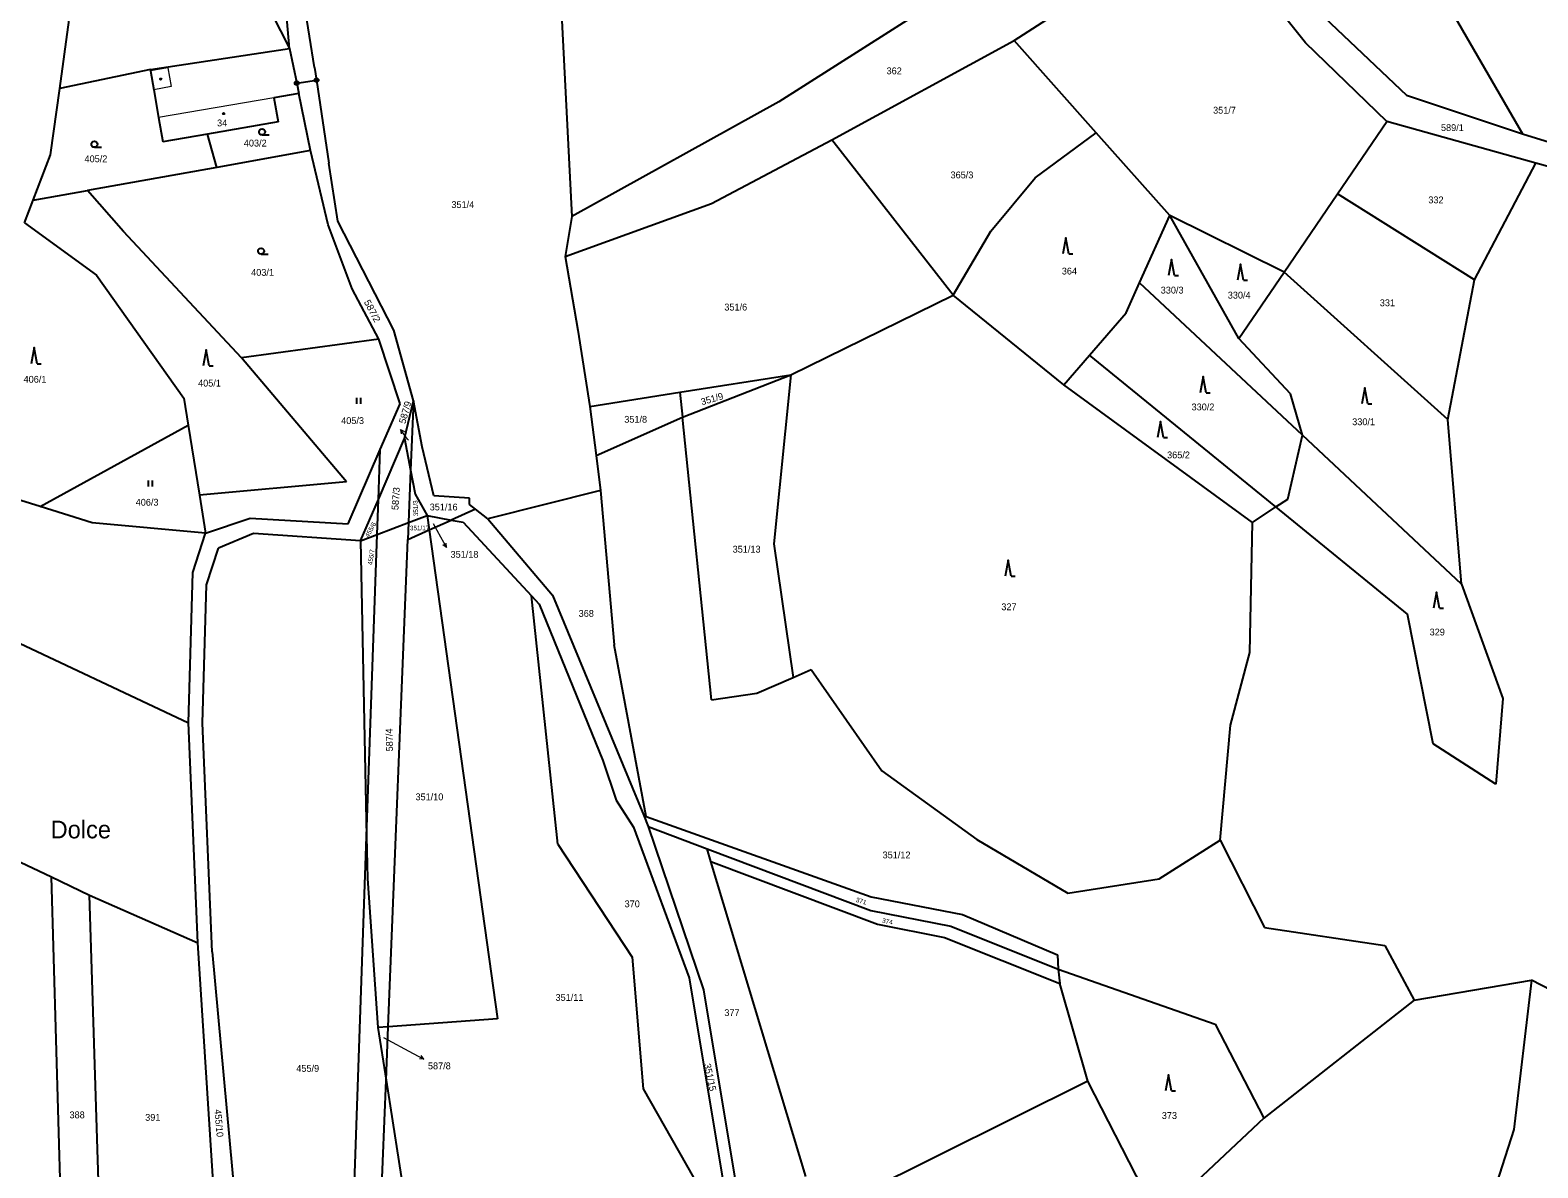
# Model space of a CAD drawing. Extents: x -664548 to -662415, y -1069720 to -1068208.
# Drawn here: x -663609.5 to -663233.8, y -1069397.8 to -1069114.5 of the extents above; entities that cross this region are included whole.
import ezdxf
from ezdxf.enums import TextEntityAlignment as Align

# ---------------------------------------------------------------- set-up
doc = ezdxf.new("R2010")
doc.units = 0
doc.header["$LTSCALE"] = 0.68
for name, color, linetype, lineweight in [('1', 7, 'Continuous', 25), ('3', 7, 'Continuous', 25), ('4', 7, 'Continuous', 13), ('5', 7, 'Continuous', 25), ('7', 7, 'Continuous', 13), ('8', 7, 'Continuous', 25)]:
    doc.layers.add(name, color=color, linetype=linetype, lineweight=lineweight)
doc.layers.add('2', color=7, linetype='Continuous')

msp = doc.modelspace()

# ---------------------------------------------------------------- linework, layer by layer
at = {"layer": '1'}
for p, q in [((-663290.69, -1069048.61), (-663237.59, -1069140.27)), ((-663562.04, -1069085.25), (-663544.88, -1069119.07)), ((-663364.35, -1069117.05), (-663316.66, -1069086.41)), ((-663291.71, -1069117.65), (-663316.66, -1069086.41)), ((-663371.11, -1069099.37), (-663422.94, -1069132.37)), ((-663544.88, -1069119.07), (-663545.93, -1069107.64)), ((-663538.64, -1069123.79), (-663541.13, -1069108.16)), ((-663477.22, -1069108.85), (-663474.57, -1069160.93)), ((-663288.57, -1069109.85), (-663266.5, -1069130.7)), ((-663602.17, -1069129.03), (-663599.82, -1069111.91)), ((-663409.77, -1069141.77), (-663364.35, -1069117.05)), ((-663343.84, -1069140.07), (-663364.35, -1069117.05)), ((-663271.46, -1069137.23), (-663291.71, -1069117.65)), ((-663579.59, -1069124.25), (-663544.88, -1069119.07)), ((-663544.88, -1069119.07), (-663543.12, -1069127.66)), ((-663579.59, -1069124.25), (-663602.17, -1069129.03)), ((-663579.59, -1069124.25), (-663579.52, -1069124.64)), ((-663579.52, -1069124.64), (-663578.7, -1069129.37)), ((-663538.64, -1069123.79), (-663538.17, -1069126.92)), ((-663604.44, -1069145.56), (-663602.17, -1069129.03)), ((-663578.7, -1069129.37), (-663577.52, -1069136.2)), ((-663543.12, -1069127.66), (-663538.17, -1069126.92)), ((-663543.12, -1069127.66), (-663542.59, -1069130.23)), ((-663538.17, -1069126.92), (-663535.09, -1069147.57)), ((-663542.59, -1069130.23), (-663548.81, -1069131.32)), ((-663548.81, -1069131.32), (-663547.77, -1069137.33)), ((-663539.64, -1069144.45), (-663542.59, -1069130.23)), ((-663422.94, -1069132.37), (-663474.57, -1069160.93)), ((-663266.5, -1069130.7), (-663237.59, -1069140.27)), ((-663577.52, -1069136.2), (-663576.47, -1069142.3)), ((-663547.77, -1069137.33), (-663565.34, -1069140.37)), ((-663283.71, -1069155.22), (-663271.46, -1069137.23)), ((-663234.3, -1069147.61), (-663271.46, -1069137.23)), ((-663565.34, -1069140.37), (-663576.47, -1069142.3)), ((-663563.03, -1069148.65), (-663565.34, -1069140.37)), ((-663359.12, -1069151.28), (-663343.84, -1069140.07)), ((-663325.5, -1069160.64), (-663343.84, -1069140.07)), ((-663237.59, -1069140.27), (-663178.99, -1069158.74)), ((-663539.64, -1069144.45), (-663563.03, -1069148.65)), ((-663535.31, -1069162.97), (-663539.64, -1069144.45)), ((-663439.71, -1069157.68), (-663409.77, -1069141.77)), ((-663379.48, -1069180.49), (-663409.77, -1069141.77)), ((-663608.81, -1069156.86), (-663604.44, -1069145.56)), ((-663563.03, -1069148.65), (-663595.24, -1069154.43)), ((-663532.83, -1069162.06), (-663535.09, -1069147.57)), ((-663249.56, -1069176.69), (-663234.3, -1069147.61)), ((-663177.21, -1069163.55), (-663234.3, -1069147.61)), ((-663370.12, -1069164.56), (-663359.12, -1069151.28)), ((-663608.81, -1069156.86), (-663595.24, -1069154.43)), ((-663297, -1069174.73), (-663283.71, -1069155.22)), ((-663249.56, -1069176.69), (-663283.71, -1069155.22)), ((-663610.98, -1069162.48), (-663608.81, -1069156.86)), ((-663476.23, -1069170.82), (-663439.71, -1069157.68)), ((-663610.98, -1069162.48), (-663593.01, -1069175.48)), ((-663529.26, -1069178.93), (-663535.31, -1069162.97)), ((-663518.87, -1069189.24), (-663532.83, -1069162.06)), ((-663474.57, -1069160.93), (-663476.23, -1069170.82)), ((-663333.06, -1069177.37), (-663325.5, -1069160.64)), ((-663297, -1069174.73), (-663325.5, -1069160.64)), ((-663308.3, -1069191.31), (-663325.5, -1069160.64)), ((-663379.48, -1069180.49), (-663370.12, -1069164.56)), ((-663476.23, -1069170.82), (-663473.06, -1069189.17)), ((-663308.3, -1069191.31), (-663297, -1069174.73)), ((-663256.27, -1069211.46), (-663297, -1069174.73)), ((-663593.01, -1069175.48), (-663571.28, -1069206.11)), ((-663522.61, -1069191.44), (-663529.26, -1069178.93)), ((-663336.44, -1069184.86), (-663333.06, -1069177.37)), ((-663292.46, -1069215.37), (-663333.06, -1069177.37)), ((-663256.27, -1069211.46), (-663249.56, -1069176.69)), ((-663419.93, -1069200.35), (-663379.48, -1069180.49)), ((-663351.9, -1069202.8), (-663379.48, -1069180.49)), ((-663345.54, -1069195.42), (-663336.44, -1069184.86)), ((-663514.04, -1069206.76), (-663518.87, -1069189.24)), ((-663473.06, -1069189.17), (-663470.04, -1069208.19)), ((-663522.61, -1069191.44), (-663556.83, -1069196.07)), ((-663517.37, -1069207.51), (-663522.61, -1069191.44)), ((-663295.44, -1069205.04), (-663308.3, -1069191.31)), ((-663530.7, -1069226.98), (-663556.83, -1069196.07)), ((-663351.9, -1069202.8), (-663345.54, -1069195.42)), ((-663299.07, -1069233.24), (-663345.54, -1069195.42)), ((-663447.64, -1069204.68), (-663419.93, -1069200.35)), ((-663447, -1069210.85), (-663419.93, -1069200.35)), ((-663419.93, -1069200.35), (-663424.2, -1069242.41)), ((-663470.04, -1069208.19), (-663447.64, -1069204.68)), ((-663447.64, -1069204.68), (-663447, -1069210.85)), ((-663304.9, -1069237.09), (-663351.9, -1069202.8)), ((-663292.46, -1069215.37), (-663295.44, -1069205.04)), ((-663571.28, -1069206.11), (-663570.19, -1069212.83)), ((-663522.32, -1069218.96), (-663517.37, -1069207.51)), ((-663516.21, -1069216.22), (-663514.04, -1069206.76)), ((-663514.04, -1069206.76), (-663514.74, -1069224.08)), ((-663511.85, -1069218.23), (-663514.04, -1069206.76)), ((-663470.04, -1069208.19), (-663468.5, -1069220.43)), ((-663607.07, -1069233.13), (-663570.19, -1069212.83)), ((-663570.19, -1069212.83), (-663567.36, -1069230.28)), ((-663468.5, -1069220.43), (-663447, -1069210.85)), ((-663439.75, -1069281.24), (-663447, -1069210.85)), ((-663252.8, -1069252.48), (-663256.27, -1069211.46)), ((-663522.76, -1069231.36), (-663516.21, -1069216.22)), ((-663516.21, -1069216.22), (-663514.74, -1069224.08)), ((-663252.8, -1069252.48), (-663292.46, -1069215.37)), ((-663530.32, -1069237.45), (-663522.32, -1069218.96)), ((-663522.76, -1069231.36), (-663522.32, -1069218.96)), ((-663508.95, -1069230.5), (-663511.85, -1069218.23)), ((-663514.74, -1069224.08), (-663515.26, -1069237.13)), ((-663514.74, -1069224.08), (-663513.62, -1069230.04)), ((-663468.5, -1069220.43), (-663467.4, -1069229.1)), ((-663530.7, -1069226.98), (-663567.36, -1069230.28)), ((-663607.07, -1069233.13), (-663620, -1069229.07)), ((-663567.36, -1069230.28), (-663565.81, -1069239.8)), ((-663527.21, -1069241.64), (-663522.76, -1069231.36)), ((-663523.07, -1069240.08), (-663522.76, -1069231.36)), ((-663513.62, -1069230.04), (-663510.62, -1069235.37)), ((-663500.08, -1069231.07), (-663508.95, -1069230.5)), ((-663500.08, -1069232.65), (-663500.08, -1069231.07)), ((-663467.4, -1069229.1), (-663495.47, -1069236.2)), ((-663467.4, -1069229.1), (-663463.99, -1069267.55)), ((-663594.1, -1069237.21), (-663607.07, -1069233.13)), ((-663515.26, -1069237.13), (-663510.62, -1069235.37)), ((-663510.62, -1069235.37), (-663510.12, -1069238.95)), ((-663510.62, -1069235.37), (-663504.58, -1069236.49)), ((-663498.57, -1069233.82), (-663504.58, -1069236.49)), ((-663498.57, -1069233.82), (-663500.08, -1069232.65)), ((-663495.47, -1069236.2), (-663498.57, -1069233.82)), ((-663304.9, -1069237.09), (-663299.07, -1069233.24)), ((-663266.27, -1069259.94), (-663299.07, -1069233.24)), ((-663565.81, -1069239.8), (-663594.1, -1069237.21)), ((-663565.81, -1069239.8), (-663554.72, -1069236.01)), ((-663554.72, -1069236.01), (-663530.32, -1069237.45)), ((-663523.07, -1069240.08), (-663515.26, -1069237.13)), ((-663515.26, -1069237.13), (-663515.43, -1069241.31)), ((-663510.12, -1069238.95), (-663493.06, -1069360.76)), ((-663504.58, -1069236.49), (-663501.66, -1069237.03)), ((-663501.66, -1069237.03), (-663484.59, -1069255.39)), ((-663495.47, -1069236.2), (-663479.37, -1069255.2)), ((-663305.57, -1069269.49), (-663304.9, -1069237.09)), ((-663568.97, -1069249.55), (-663565.81, -1069239.8)), ((-663553.89, -1069239.86), (-663562.6, -1069243.53)), ((-663527.21, -1069241.64), (-663553.89, -1069239.86)), ((-663527.21, -1069241.64), (-663523.07, -1069240.08)), ((-663527.21, -1069241.64), (-663525.71, -1069315.33)), ((-663525.71, -1069315.33), (-663523.07, -1069240.08)), ((-663520.3, -1069362.69), (-663515.43, -1069241.31)), ((-663424.2, -1069242.41), (-663419.42, -1069275.68)), ((-663565.56, -1069252.65), (-663562.6, -1069243.53)), ((-663570.12, -1069287), (-663568.97, -1069249.55)), ((-663566.61, -1069287.11), (-663565.56, -1069252.65)), ((-663252.8, -1069252.48), (-663242.55, -1069280.91)), ((-663478.06, -1069317.22), (-663484.59, -1069255.39)), ((-663484.59, -1069255.39), (-663482.65, -1069257.48)), ((-663482.65, -1069257.48), (-663466.81, -1069296.42)), ((-663479.37, -1069255.2), (-663456.64, -1069310.09)), ((-663259.93, -1069292.26), (-663266.27, -1069259.94)), ((-663620.38, -1069263.31), (-663570.12, -1069287)), ((-663456.03, -1069310.31), (-663463.99, -1069267.55)), ((-663310.38, -1069287.58), (-663305.57, -1069269.49)), ((-663428.41, -1069279.64), (-663419.42, -1069275.68)), ((-663419.42, -1069275.68), (-663414.92, -1069273.69)), ((-663414.92, -1069273.69), (-663397.26, -1069298.97)), ((-663439.75, -1069281.24), (-663428.41, -1069279.64)), ((-663242.55, -1069280.91), (-663244.28, -1069302.3)), ((-663567.74, -1069341.82), (-663570.12, -1069287)), ((-663564.14, -1069344.05), (-663566.61, -1069287.11)), ((-663312.95, -1069316.19), (-663310.38, -1069287.58)), ((-663244.28, -1069302.3), (-663259.93, -1069292.26)), ((-663466.81, -1069296.42), (-663463.52, -1069306.28)), ((-663397.26, -1069298.97), (-663373.63, -1069316.04)), ((-663463.52, -1069306.28), (-663459.22, -1069312.98)), ((-663456.64, -1069310.09), (-663456.03, -1069310.31)), ((-663456.64, -1069310.09), (-663455.52, -1069312.82)), ((-663456.03, -1069310.31), (-663399.91, -1069330.35)), ((-663459.22, -1069312.98), (-663445.32, -1069350.54)), ((-663455.52, -1069312.82), (-663441.76, -1069353.53)), ((-663455.52, -1069312.82), (-663440.82, -1069318.37)), ((-663533.54, -1069538.23), (-663525.71, -1069315.33)), ((-663525.71, -1069315.33), (-663525.5, -1069325.78)), ((-663478.06, -1069317.22), (-663459.53, -1069345.4)), ((-663373.63, -1069316.04), (-663350.9, -1069329.44)), ((-663328.15, -1069325.88), (-663312.95, -1069316.19)), ((-663312.95, -1069316.19), (-663301.93, -1069338)), ((-663613.49, -1069320.97), (-663604.26, -1069325.38)), ((-663439.87, -1069321.52), (-663440.82, -1069318.37)), ((-663439.87, -1069321.52), (-663398.4, -1069337.17)), ((-663416.26, -1069400.01), (-663439.87, -1069321.52)), ((-663604.26, -1069325.38), (-663594.75, -1069329.92)), ((-663601.1, -1069432.51), (-663604.26, -1069325.38)), ((-663525.5, -1069325.78), (-663522.87, -1069362.87)), ((-663350.9, -1069329.44), (-663328.15, -1069325.88)), ((-663594.75, -1069329.92), (-663567.74, -1069341.82)), ((-663591.5, -1069432.04), (-663594.75, -1069329.92)), ((-663399.91, -1069330.35), (-663377.19, -1069334.75)), ((-663377.19, -1069334.75), (-663353.55, -1069344.77)), ((-663398.4, -1069337.17), (-663381.65, -1069340.44)), ((-663381.65, -1069340.44), (-663352.91, -1069351.95)), ((-663380.06, -1069337.68), (-663353.34, -1069348.38)), ((-663301.93, -1069338), (-663271.97, -1069342.43)), ((-663562.07, -1069430.61), (-663567.74, -1069341.82)), ((-663564.14, -1069344.05), (-663556.21, -1069430.9)), ((-663271.97, -1069342.43), (-663264.64, -1069356.09)), ((-663459.53, -1069345.4), (-663456.74, -1069378.18)), ((-663353.55, -1069344.77), (-663353.34, -1069348.38)), ((-663445.32, -1069350.54), (-663434.06, -1069418.05)), ((-663353.34, -1069348.38), (-663314.26, -1069362.06)), ((-663353.34, -1069348.38), (-663352.91, -1069351.95)), ((-663264.64, -1069356.09), (-663235.38, -1069351.09)), ((-663235.38, -1069351.09), (-663239.78, -1069388.33)), ((-663213.09, -1069362.7), (-663235.38, -1069351.09)), ((-663441.76, -1069353.53), (-663432.72, -1069407.43)), ((-663345.95, -1069376.22), (-663352.91, -1069351.95)), ((-663264.64, -1069356.09), (-663302.13, -1069385.5)), ((-663520.3, -1069362.69), (-663522.87, -1069362.87)), ((-663522.87, -1069362.87), (-663520.83, -1069375.97)), ((-663520.83, -1069375.97), (-663520.3, -1069362.69)), ((-663493.06, -1069360.76), (-663520.3, -1069362.69)), ((-663314.26, -1069362.06), (-663302.13, -1069385.5)), ((-663527.43, -1069540.73), (-663520.83, -1069375.97)), ((-663520.83, -1069375.97), (-663510.43, -1069442.65)), ((-663456.74, -1069378.18), (-663434.06, -1069418.05)), ((-663345.95, -1069376.22), (-663402.37, -1069404.33)), ((-663328.48, -1069410.22), (-663345.95, -1069376.22)), ((-663302.13, -1069385.5), (-663328.48, -1069410.22)), ((-663239.78, -1069388.33), (-663255.97, -1069438.48))]:
    msp.add_line(p, q, dxfattribs=at)
for points in [[(-663556.83, -1069196.07), (-663586.28, -1069164.65), (-663595.24, -1069154.43)], [(-663299.07, -1069233.24), (-663296.08, -1069231.26), (-663292.46, -1069215.37)], [(-663515.43, -1069241.31), (-663510.12, -1069238.95), (-663504.58, -1069236.49)], [(-663440.82, -1069318.37), (-663400, -1069333.78), (-663380.06, -1069337.68)]]:
    msp.add_lwpolyline(points, dxfattribs=at)
at = {"layer": '3'}
for p, q in [((-663551.743, -1069140.58), (-663549.993, -1069140.58)), ((-663593.533, -1069143.64), (-663591.783, -1069143.64)), ((-663552.003, -1069170.27), (-663550.253, -1069170.27)), ((-663350.72, -1069170.17), (-663349.724, -1069170.17)), ((-663324.39, -1069175.61), (-663323.394, -1069175.61)), ((-663307.12, -1069176.72), (-663306.124, -1069176.72)), ((-663607.76, -1069197.55), (-663606.764, -1069197.55)), ((-663564.91, -1069198.07), (-663563.914, -1069198.07)), ((-663316.48, -1069204.77), (-663315.484, -1069204.77)), ((-663528.151, -1069207.58), (-663528.151, -1069206.08)), ((-663527.15, -1069207.58), (-663527.15, -1069206.08)), ((-663276.15, -1069207.56), (-663275.154, -1069207.56)), ((-663327.12, -1069215.96), (-663326.124, -1069215.96)), ((-663580.051, -1069228.17), (-663580.051, -1069226.67)), ((-663579.05, -1069228.17), (-663579.05, -1069226.67)), ((-663365.05, -1069250.48), (-663364.054, -1069250.48)), ((-663258.31, -1069258.47), (-663257.314, -1069258.47)), ((-663325.07, -1069378.64), (-663324.074, -1069378.64))]:
    msp.add_line(p, q, dxfattribs=at)
for points in [[(-663350.72, -1069170.17), (-663351.47, -1069166.17), (-663352.22, -1069170.17)], [(-663324.39, -1069175.61), (-663325.14, -1069171.61), (-663325.89, -1069175.61)], [(-663307.12, -1069176.72), (-663307.87, -1069172.72), (-663308.62, -1069176.72)], [(-663607.76, -1069197.55), (-663608.51, -1069193.55), (-663609.26, -1069197.55)], [(-663564.91, -1069198.07), (-663565.66, -1069194.07), (-663566.41, -1069198.07)], [(-663316.48, -1069204.77), (-663317.23, -1069200.77), (-663317.98, -1069204.77)], [(-663276.15, -1069207.56), (-663276.9, -1069203.56), (-663277.65, -1069207.56)], [(-663327.12, -1069215.96), (-663327.87, -1069211.96), (-663328.62, -1069215.96)], [(-663365.05, -1069250.48), (-663365.8, -1069246.48), (-663366.55, -1069250.48)], [(-663258.31, -1069258.47), (-663259.06, -1069254.47), (-663259.81, -1069258.47)], [(-663325.07, -1069378.64), (-663325.82, -1069374.64), (-663326.57, -1069378.64)]]:
    msp.add_lwpolyline(points, dxfattribs=at)
for centre in [(-663551.7429, -1069139.8298), (-663593.5329, -1069142.8898), (-663552.0029, -1069169.5198)]:
    msp.add_circle(centre, 0.75, dxfattribs=at)
at = {"layer": '4'}
for p, q in [((-663575.26, -1069123.82), (-663579.52, -1069124.64)), ((-663575.26, -1069123.82), (-663574.44, -1069128.55)), ((-663574.44, -1069128.55), (-663578.7, -1069129.37)), ((-663548.81, -1069131.32), (-663577.52, -1069136.2))]:
    msp.add_line(p, q, dxfattribs=at)
at = {"layer": '5'}
for centre in [(-663576.9968, -1069126.6592), (-663561.3068, -1069135.2492)]:
    msp.add_circle(centre, 0.175, dxfattribs=at)
at = {"layer": '7'}
for p, q in [((-663517.266, -1069213.933), (-663517.063, -1069215.034)), ((-663505.795, -1069243.335), (-663505.843, -1069242.216)), ((-663511.41, -1069370.739), (-663512.059, -1069369.827))]:
    msp.add_line(p, q, dxfattribs=at)
for points in [[(-663515.24, -1069216.62), (-663515.46, -1069216.33), (-663517.266, -1069213.933), (-663516.263, -1069214.432)], [(-663509.13, -1069237.37), (-663507.25, -1069240.71), (-663505.795, -1069243.335), (-663506.719, -1069242.702)], [(-663521.48, -1069365.4), (-663514.06, -1069369.33), (-663511.41, -1069370.739), (-663512.53, -1069370.711)]]:
    msp.add_lwpolyline(points, dxfattribs=at)
at = {"layer": '8'}
for centre, radius in [((-663538.17, -1069126.9199), 0.5), ((-663543.12, -1069127.6599), 0.5), ((-663543.12, -1069127.6599), 0.0303), ((-663538.17, -1069126.9199), 0.0303)]:
    msp.add_circle(centre, radius, dxfattribs=at)

# ---------------------------------------------------------------- texts
at = {"layer": '2'}
for s, height, p in [('362', 1.7, (-663396.11, -1069125.465)), ('351/7', 1.7, (-663314.74, -1069135.265)), ('34', 1.7, (-663562.96, -1069138.435)), ('403/2', 1.7, (-663556.29, -1069143.455)), ('405/2', 1.7, (-663595.99, -1069147.375)), ('365/3', 1.7, (-663380.17, -1069151.385)), ('332', 1.7, (-663261.1, -1069157.604)), ('351/4', 1.7, (-663504.56, -1069158.775)), ('403/1', 1.7, (-663554.46, -1069175.655)), ('364', 1.7, (-663352.44, -1069175.334)), ('330/3', 1.7, (-663327.79, -1069180.074)), ('351/6', 1.7, (-663436.54, -1069184.304)), ('330/4', 1.7, (-663311.08, -1069181.324)), ('331', 1.7, (-663273.19, -1069183.235)), ('406/1', 1.7, (-663611.18, -1069202.285)), ('405/1', 1.7, (-663567.69, -1069203.245)), ('330/2', 1.7, (-663320.1, -1069209.175)), ('405/3', 1.7, (-663532.03, -1069212.574)), ('351/8', 1.7, (-663461.48, -1069212.255)), ('330/1', 1.7, (-663280.07, -1069212.865)), ('365/2', 1.7, (-663326.2, -1069221.125)), ('406/3', 1.7, (-663583.24, -1069232.915)), ('351/16', 1.7, (-663509.97, -1069234.094)), ('351/17', 1.14, (-663514.89, -1069239.045)), ('351/13', 1.7, (-663434.47, -1069244.604)), ('351/18', 1.7, (-663504.78, -1069245.885)), ('327', 1.7, (-663367.51, -1069258.955)), ('368', 1.7, (-663472.85, -1069260.604)), ('329', 1.7, (-663260.77, -1069265.235)), ('351/10', 1.7, (-663513.52, -1069306.285)), ('351/12', 1.7, (-663397.1, -1069320.755)), ('370', 1.7, (-663461.4, -1069332.935)), ('351/11', 1.7, (-663478.62, -1069356.255)), ('377', 1.7, (-663436.54, -1069360.035)), ('455/9', 1.7, (-663543.21, -1069373.915)), ('587/8', 1.7, (-663510.41, -1069373.295)), ('388', 1.7, (-663599.73, -1069385.495)), ('391', 1.7, (-663580.87, -1069386.115)), ('373', 1.7, (-663327.52, -1069385.655))]:
    msp.add_text(s, height=height, dxfattribs=at).set_placement(p)
msp.add_text('589/1', height=1.7, dxfattribs=at).set_placement((-663255.1, -1069139.604), align=Align.CENTER)
at = {"layer": '2', "width": 1.05}
msp.add_text('587/2', height=1.7, rotation=298, dxfattribs=at).set_placement((-663525.0264, -1069184.8224), align=Align.CENTER)
at = {"layer": '2'}
for s, height, rotation, p in [('351/9', 1.7, 16, (-663442.112, -1069207.918)), ('587/3', 1.7, 86, (-663517.786, -1069234.059)), ('351/3', 1.14, 92, (-663512.845, -1069235.52)), ('455/7', 1.14, 82, (-663524.277, -1069247.779)), ('587/4', 1.7, 91, (-663519.125, -1069294.102)), ('374', 1.14, 349, (-663397.294, -1069336.769)), ('351/15', 1.7, 282, (-663441.625, -1069372.058)), ('455/10', 1.7, 275, (-663563.643, -1069383.317))]:
    msp.add_text(s, height=height, rotation=rotation, dxfattribs=at).set_placement(p)
msp.add_text('587/9', height=1.7, rotation=74, dxfattribs=at).set_placement((-663514.492, -1069207.1776), align=Align.RIGHT)
at = {"layer": '2', "width": 1.05}
for s, rotation, p in [('455/6', 61, (-663525.18, -1069240.928)), ('371', 344, (-663403.858, -1069331.573))]:
    msp.add_text(s, height=1.14, rotation=rotation, dxfattribs=at).set_placement(p)
at = {"layer": '7'}
msp.add_text('Dolce', height=4.4, dxfattribs=at).set_placement((-663596.919, -1069315.77), align=Align.CENTER)

doc.saveas('drawing.dxf')
